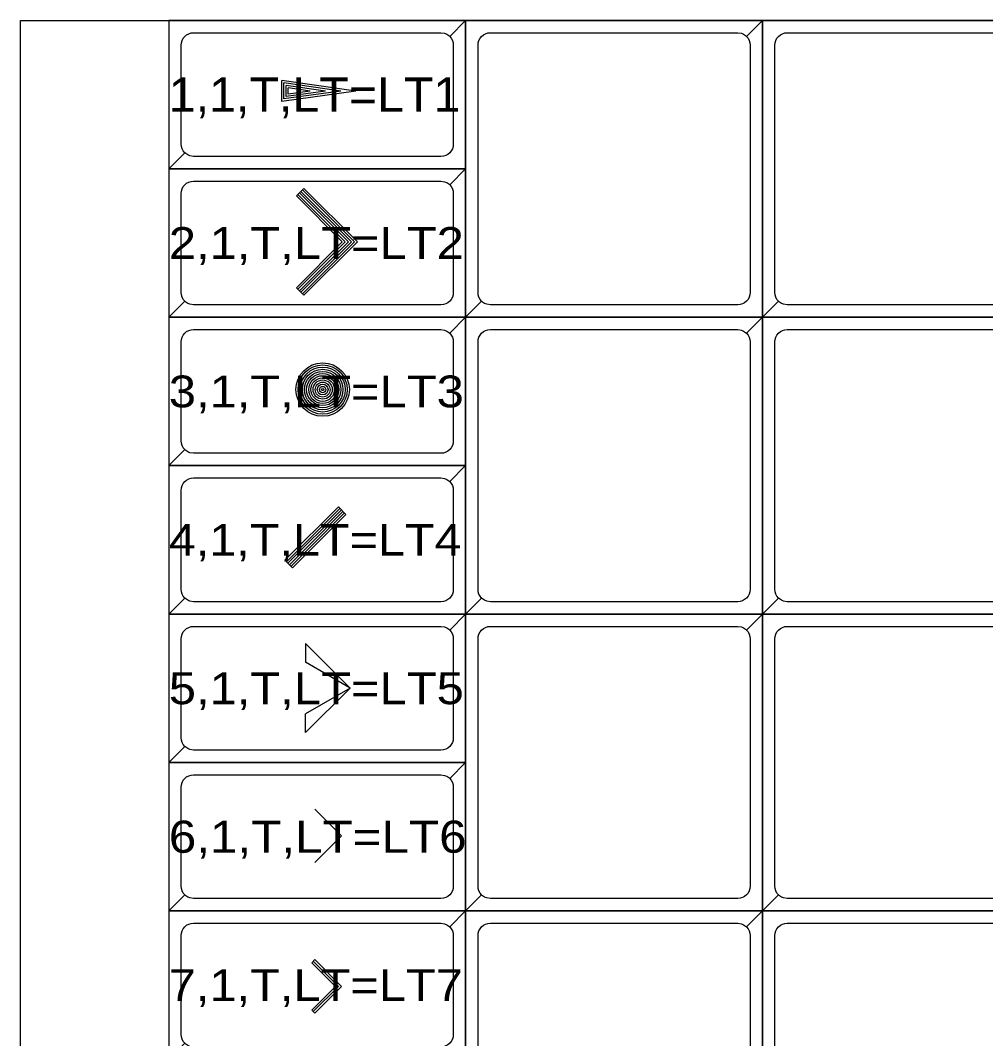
# Model space of a CAD drawing. Extents: x 67896 to 67908, y 49158.5 to 49162.6.
# Drawn here: x 67895.989 to 67897.94, y 49160.575 to 49162.633 of the extents above; entities that cross this region are included whole.
import ezdxf

# ---------------------------------------------------------------- set-up
doc = ezdxf.new("R2010")
doc.units = 0
doc.header["$LTSCALE"] = 0.02
for name, color, linetype, lineweight in [('1', 7, 'Continuous', 25), ('2', 7, 'Continuous', 25), ('3', 7, 'Continuous', 25), ('4', 7, 'Continuous', 25), ('5', 7, 'Continuous', 25)]:
    doc.layers.add(name, color=color, linetype=linetype, lineweight=lineweight)
doc.layers.add('63', color=7, linetype='Continuous')

msp = doc.modelspace()

# ---------------------------------------------------------------- linework, layer by layer
at = {"layer": '1'}
for points in [[(67896.2889, 49162.3331), (67896.8889, 49162.3331), (67896.8889, 49162.6331), (67896.2889, 49162.6331)], [(67896.8889, 49162.0331), (67897.4889, 49162.0331), (67897.4889, 49162.6331), (67896.8889, 49162.6331)], [(67897.4889, 49162.0331), (67898.0889, 49162.0331), (67898.0889, 49162.6331), (67897.4889, 49162.6331)], [(67896.2889, 49162.0331), (67896.8889, 49162.0331), (67896.8889, 49162.3331), (67896.2889, 49162.3331)], [(67896.2889, 49161.7331), (67896.8889, 49161.7331), (67896.8889, 49162.0331), (67896.2889, 49162.0331)], [(67896.8889, 49161.4331), (67897.4889, 49161.4331), (67897.4889, 49162.0331), (67896.8889, 49162.0331)], [(67897.4889, 49161.4331), (67898.0889, 49161.4331), (67898.0889, 49162.0331), (67897.4889, 49162.0331)], [(67896.2889, 49161.4331), (67896.8889, 49161.4331), (67896.8889, 49161.7331), (67896.2889, 49161.7331)], [(67896.2889, 49161.1331), (67896.8889, 49161.1331), (67896.8889, 49161.4331), (67896.2889, 49161.4331)], [(67896.8889, 49160.8331), (67897.4889, 49160.8331), (67897.4889, 49161.4331), (67896.8889, 49161.4331)], [(67897.4889, 49160.8331), (67898.0889, 49160.8331), (67898.0889, 49161.4331), (67897.4889, 49161.4331)], [(67896.2889, 49160.8331), (67896.8889, 49160.8331), (67896.8889, 49161.1331), (67896.2889, 49161.1331)], [(67896.2889, 49160.5331), (67896.8889, 49160.5331), (67896.8889, 49160.8331), (67896.2889, 49160.8331)], [(67896.8889, 49160.2331), (67897.4889, 49160.2331), (67897.4889, 49160.8331), (67896.8889, 49160.8331)], [(67897.4889, 49160.2331), (67898.0889, 49160.2331), (67898.0889, 49160.8331), (67897.4889, 49160.8331)]]:
    msp.add_lwpolyline(points, close=True, dxfattribs=at)
at = {"layer": '2'}
for points in [[(67907.9889, 49159.0331), (67895.9889, 49159.0331), (67895.9889, 49162.6331), (67907.9889, 49162.6331)], [(67896.2889, 49162.3331), (67896.8889, 49162.3331), (67896.8889, 49162.6331), (67896.2889, 49162.6331)], [(67896.8889, 49162.0331), (67897.4889, 49162.0331), (67897.4889, 49162.6331), (67896.8889, 49162.6331)], [(67897.4889, 49162.0331), (67898.0889, 49162.0331), (67898.0889, 49162.6331), (67897.4889, 49162.6331)], [(67896.2889, 49162.0331), (67896.8889, 49162.0331), (67896.8889, 49162.3331), (67896.2889, 49162.3331)], [(67896.2889, 49161.7331), (67896.8889, 49161.7331), (67896.8889, 49162.0331), (67896.2889, 49162.0331)], [(67896.8889, 49161.4331), (67897.4889, 49161.4331), (67897.4889, 49162.0331), (67896.8889, 49162.0331)], [(67897.4889, 49161.4331), (67898.0889, 49161.4331), (67898.0889, 49162.0331), (67897.4889, 49162.0331)], [(67896.2889, 49161.4331), (67896.8889, 49161.4331), (67896.8889, 49161.7331), (67896.2889, 49161.7331)], [(67896.2889, 49161.1331), (67896.8889, 49161.1331), (67896.8889, 49161.4331), (67896.2889, 49161.4331)], [(67896.8889, 49160.8331), (67897.4889, 49160.8331), (67897.4889, 49161.4331), (67896.8889, 49161.4331)], [(67897.4889, 49160.8331), (67898.0889, 49160.8331), (67898.0889, 49161.4331), (67897.4889, 49161.4331)], [(67896.2889, 49160.8331), (67896.8889, 49160.8331), (67896.8889, 49161.1331), (67896.2889, 49161.1331)], [(67896.2889, 49160.5331), (67896.8889, 49160.5331), (67896.8889, 49160.8331), (67896.2889, 49160.8331)], [(67896.8889, 49160.2331), (67897.4889, 49160.2331), (67897.4889, 49160.8331), (67896.8889, 49160.8331)], [(67897.4889, 49160.2331), (67898.0889, 49160.2331), (67898.0889, 49160.8331), (67897.4889, 49160.8331)]]:
    msp.add_lwpolyline(points, close=True, dxfattribs=at)
at = {"layer": '3'}
for points in [[(67896.8889, 49162.6331), (67896.2889, 49162.6331), (67896.2889, 49162.3331), (67896.3212, 49162.3654), (67896.3181, 49162.3692), (67896.3158, 49162.3735), (67896.3144, 49162.3782), (67896.3139, 49162.3831), (67896.3139, 49162.5831), (67896.3144, 49162.588), (67896.3158, 49162.5927), (67896.3181, 49162.597), (67896.3212, 49162.6008), (67896.3212, 49162.6008), (67896.325, 49162.6039), (67896.3293, 49162.6062), (67896.334, 49162.6076), (67896.3389, 49162.6081), (67896.8389, 49162.6081), (67896.8462, 49162.607), (67896.8507, 49162.6051), (67896.8548, 49162.6024), (67896.8566, 49162.6008)], [(67897.4889, 49162.6331), (67896.8889, 49162.6331), (67896.8889, 49162.0331), (67896.9212, 49162.0654), (67896.9181, 49162.0692), (67896.9158, 49162.0735), (67896.9144, 49162.0782), (67896.9139, 49162.0831), (67896.9139, 49162.5831), (67896.9144, 49162.588), (67896.9158, 49162.5927), (67896.9181, 49162.597), (67896.9212, 49162.6008), (67896.9212, 49162.6008), (67896.925, 49162.6039), (67896.9293, 49162.6062), (67896.934, 49162.6076), (67896.9389, 49162.6081), (67897.4389, 49162.6081), (67897.4462, 49162.607), (67897.4507, 49162.6051), (67897.4548, 49162.6024), (67897.4566, 49162.6008)], [(67898.0889, 49162.6331), (67897.4889, 49162.6331), (67897.4889, 49162.0331), (67897.5212, 49162.0654), (67897.5181, 49162.0692), (67897.5158, 49162.0735), (67897.5144, 49162.0782), (67897.5139, 49162.0831), (67897.5139, 49162.5831), (67897.5144, 49162.588), (67897.5158, 49162.5927), (67897.5181, 49162.597), (67897.5212, 49162.6008), (67897.5212, 49162.6008), (67897.525, 49162.6039), (67897.5293, 49162.6062), (67897.534, 49162.6076), (67897.5389, 49162.6081), (67898.0389, 49162.6081), (67898.0462, 49162.607), (67898.0507, 49162.6051), (67898.0548, 49162.6024), (67898.0566, 49162.6008)], [(67896.8889, 49162.3331), (67896.2889, 49162.3331), (67896.2889, 49162.0331), (67896.3212, 49162.0654), (67896.3181, 49162.0692), (67896.3158, 49162.0735), (67896.3144, 49162.0782), (67896.3139, 49162.0831), (67896.3139, 49162.2831), (67896.3144, 49162.288), (67896.3158, 49162.2927), (67896.3181, 49162.297), (67896.3212, 49162.3008), (67896.3212, 49162.3008), (67896.325, 49162.3039), (67896.3293, 49162.3062), (67896.334, 49162.3076), (67896.3389, 49162.3081), (67896.8389, 49162.3081), (67896.8462, 49162.307), (67896.8507, 49162.3051), (67896.8548, 49162.3024), (67896.8566, 49162.3008)], [(67896.8889, 49162.0331), (67896.2889, 49162.0331), (67896.2889, 49161.7331), (67896.3212, 49161.7654), (67896.3181, 49161.7692), (67896.3158, 49161.7735), (67896.3144, 49161.7782), (67896.3139, 49161.7831), (67896.3139, 49161.9831), (67896.3144, 49161.988), (67896.3158, 49161.9927), (67896.3181, 49161.997), (67896.3212, 49162.0008), (67896.3212, 49162.0008), (67896.325, 49162.0039), (67896.3293, 49162.0062), (67896.334, 49162.0076), (67896.3389, 49162.0081), (67896.8389, 49162.0081), (67896.8462, 49162.007), (67896.8507, 49162.0051), (67896.8548, 49162.0024), (67896.8566, 49162.0008)], [(67897.4889, 49162.0331), (67896.8889, 49162.0331), (67896.8889, 49161.4331), (67896.9212, 49161.4654), (67896.9181, 49161.4692), (67896.9158, 49161.4735), (67896.9144, 49161.4782), (67896.9139, 49161.4831), (67896.9139, 49161.9831), (67896.9144, 49161.988), (67896.9158, 49161.9927), (67896.9181, 49161.997), (67896.9212, 49162.0008), (67896.9212, 49162.0008), (67896.925, 49162.0039), (67896.9293, 49162.0062), (67896.934, 49162.0076), (67896.9389, 49162.0081), (67897.4389, 49162.0081), (67897.4462, 49162.007), (67897.4507, 49162.0051), (67897.4548, 49162.0024), (67897.4566, 49162.0008)], [(67898.0889, 49162.0331), (67897.4889, 49162.0331), (67897.4889, 49161.4331), (67897.5212, 49161.4654), (67897.5181, 49161.4692), (67897.5158, 49161.4735), (67897.5144, 49161.4782), (67897.5139, 49161.4831), (67897.5139, 49161.9831), (67897.5144, 49161.988), (67897.5158, 49161.9927), (67897.5181, 49161.997), (67897.5212, 49162.0008), (67897.5212, 49162.0008), (67897.525, 49162.0039), (67897.5293, 49162.0062), (67897.534, 49162.0076), (67897.5389, 49162.0081), (67898.0389, 49162.0081), (67898.0462, 49162.007), (67898.0507, 49162.0051), (67898.0548, 49162.0024), (67898.0566, 49162.0008)], [(67896.8889, 49161.7331), (67896.2889, 49161.7331), (67896.2889, 49161.4331), (67896.3212, 49161.4654), (67896.3181, 49161.4692), (67896.3158, 49161.4735), (67896.3144, 49161.4782), (67896.3139, 49161.4831), (67896.3139, 49161.6831), (67896.3144, 49161.688), (67896.3158, 49161.6927), (67896.3181, 49161.697), (67896.3212, 49161.7008), (67896.3212, 49161.7008), (67896.325, 49161.7039), (67896.3293, 49161.7062), (67896.334, 49161.7076), (67896.3389, 49161.7081), (67896.8389, 49161.7081), (67896.8462, 49161.707), (67896.8507, 49161.7051), (67896.8548, 49161.7024), (67896.8566, 49161.7008)], [(67896.8889, 49161.4331), (67896.2889, 49161.4331), (67896.2889, 49161.1331), (67896.3212, 49161.1654), (67896.3181, 49161.1692), (67896.3158, 49161.1735), (67896.3144, 49161.1782), (67896.3139, 49161.1831), (67896.3139, 49161.3831), (67896.3144, 49161.388), (67896.3158, 49161.3927), (67896.3181, 49161.397), (67896.3212, 49161.4008), (67896.3212, 49161.4008), (67896.325, 49161.4039), (67896.3293, 49161.4062), (67896.334, 49161.4076), (67896.3389, 49161.4081), (67896.8389, 49161.4081), (67896.8462, 49161.407), (67896.8507, 49161.4051), (67896.8548, 49161.4024), (67896.8566, 49161.4008)], [(67897.4889, 49161.4331), (67896.8889, 49161.4331), (67896.8889, 49160.8331), (67896.9212, 49160.8654), (67896.9181, 49160.8692), (67896.9158, 49160.8735), (67896.9144, 49160.8782), (67896.9139, 49160.8831), (67896.9139, 49161.3831), (67896.9144, 49161.388), (67896.9158, 49161.3927), (67896.9181, 49161.397), (67896.9212, 49161.4008), (67896.9212, 49161.4008), (67896.925, 49161.4039), (67896.9293, 49161.4062), (67896.934, 49161.4076), (67896.9389, 49161.4081), (67897.4389, 49161.4081), (67897.4462, 49161.407), (67897.4507, 49161.4051), (67897.4548, 49161.4024), (67897.4566, 49161.4008)], [(67898.0889, 49161.4331), (67897.4889, 49161.4331), (67897.4889, 49160.8331), (67897.5212, 49160.8654), (67897.5181, 49160.8692), (67897.5158, 49160.8735), (67897.5144, 49160.8782), (67897.5139, 49160.8831), (67897.5139, 49161.3831), (67897.5144, 49161.388), (67897.5158, 49161.3927), (67897.5181, 49161.397), (67897.5212, 49161.4008), (67897.5212, 49161.4008), (67897.525, 49161.4039), (67897.5293, 49161.4062), (67897.534, 49161.4076), (67897.5389, 49161.4081), (67898.0389, 49161.4081), (67898.0462, 49161.407), (67898.0507, 49161.4051), (67898.0548, 49161.4024), (67898.0566, 49161.4008)], [(67896.8889, 49161.1331), (67896.2889, 49161.1331), (67896.2889, 49160.8331), (67896.3212, 49160.8654), (67896.3181, 49160.8692), (67896.3158, 49160.8735), (67896.3144, 49160.8782), (67896.3139, 49160.8831), (67896.3139, 49161.0831), (67896.3144, 49161.088), (67896.3158, 49161.0927), (67896.3181, 49161.097), (67896.3212, 49161.1008), (67896.3212, 49161.1008), (67896.325, 49161.1039), (67896.3293, 49161.1062), (67896.334, 49161.1076), (67896.3389, 49161.1081), (67896.8389, 49161.1081), (67896.8462, 49161.107), (67896.8507, 49161.1051), (67896.8548, 49161.1024), (67896.8566, 49161.1008)], [(67896.8889, 49160.8331), (67896.2889, 49160.8331), (67896.2889, 49160.5331), (67896.3212, 49160.5654), (67896.3181, 49160.5692), (67896.3158, 49160.5735), (67896.3144, 49160.5782), (67896.3139, 49160.5831), (67896.3139, 49160.7831), (67896.3144, 49160.788), (67896.3158, 49160.7927), (67896.3181, 49160.797), (67896.3212, 49160.8008), (67896.3212, 49160.8008), (67896.325, 49160.8039), (67896.3293, 49160.8062), (67896.334, 49160.8076), (67896.3389, 49160.8081), (67896.8389, 49160.8081), (67896.8462, 49160.807), (67896.8507, 49160.8051), (67896.8548, 49160.8024), (67896.8566, 49160.8008)], [(67897.4889, 49160.8331), (67896.8889, 49160.8331), (67896.8889, 49160.2331), (67896.9212, 49160.2654), (67896.9181, 49160.2692), (67896.9158, 49160.2735), (67896.9144, 49160.2782), (67896.9139, 49160.2831), (67896.9139, 49160.7831), (67896.9144, 49160.788), (67896.9158, 49160.7927), (67896.9181, 49160.797), (67896.9212, 49160.8008), (67896.9212, 49160.8008), (67896.925, 49160.8039), (67896.9293, 49160.8062), (67896.934, 49160.8076), (67896.9389, 49160.8081), (67897.4389, 49160.8081), (67897.4462, 49160.807), (67897.4507, 49160.8051), (67897.4548, 49160.8024), (67897.4566, 49160.8008)], [(67898.0889, 49160.8331), (67897.4889, 49160.8331), (67897.4889, 49160.2331), (67897.5212, 49160.2654), (67897.5181, 49160.2692), (67897.5158, 49160.2735), (67897.5144, 49160.2782), (67897.5139, 49160.2831), (67897.5139, 49160.7831), (67897.5144, 49160.788), (67897.5158, 49160.7927), (67897.5181, 49160.797), (67897.5212, 49160.8008), (67897.5212, 49160.8008), (67897.525, 49160.8039), (67897.5293, 49160.8062), (67897.534, 49160.8076), (67897.5389, 49160.8081), (67898.0389, 49160.8081), (67898.0462, 49160.807), (67898.0507, 49160.8051), (67898.0548, 49160.8024), (67898.0566, 49160.8008)]]:
    msp.add_lwpolyline(points, close=True, dxfattribs=at)
at = {"layer": '4'}
for points in [[(67896.2889, 49162.3331), (67896.8889, 49162.3331), (67896.8889, 49162.6331), (67896.8566, 49162.6008), (67896.8597, 49162.597), (67896.862, 49162.5927), (67896.8634, 49162.588), (67896.8639, 49162.5831), (67896.8639, 49162.3831), (67896.8634, 49162.3782), (67896.862, 49162.3735), (67896.8597, 49162.3692), (67896.8566, 49162.3654), (67896.8566, 49162.3654), (67896.8528, 49162.3623), (67896.8485, 49162.36), (67896.8438, 49162.3586), (67896.8389, 49162.3581), (67896.3389, 49162.3581), (67896.3316, 49162.3592), (67896.3271, 49162.3611), (67896.323, 49162.3638), (67896.3212, 49162.3654)], [(67896.8889, 49162.0331), (67897.4889, 49162.0331), (67897.4889, 49162.6331), (67897.4566, 49162.6008), (67897.4597, 49162.597), (67897.462, 49162.5927), (67897.4634, 49162.588), (67897.4639, 49162.5831), (67897.4639, 49162.0831), (67897.4634, 49162.0782), (67897.462, 49162.0735), (67897.4597, 49162.0692), (67897.4566, 49162.0654), (67897.4566, 49162.0654), (67897.4528, 49162.0623), (67897.4485, 49162.06), (67897.4438, 49162.0586), (67897.4389, 49162.0581), (67896.9389, 49162.0581), (67896.9316, 49162.0592), (67896.9271, 49162.0611), (67896.923, 49162.0638), (67896.9212, 49162.0654)], [(67897.4889, 49162.0331), (67898.0889, 49162.0331), (67898.0889, 49162.6331), (67898.0566, 49162.6008), (67898.0597, 49162.597), (67898.062, 49162.5927), (67898.0634, 49162.588), (67898.0639, 49162.5831), (67898.0639, 49162.0831), (67898.0634, 49162.0782), (67898.062, 49162.0735), (67898.0597, 49162.0692), (67898.0566, 49162.0654), (67898.0566, 49162.0654), (67898.0528, 49162.0623), (67898.0485, 49162.06), (67898.0438, 49162.0586), (67898.0389, 49162.0581), (67897.5389, 49162.0581), (67897.5316, 49162.0592), (67897.5271, 49162.0611), (67897.523, 49162.0638), (67897.5212, 49162.0654)], [(67896.2889, 49162.0331), (67896.8889, 49162.0331), (67896.8889, 49162.3331), (67896.8566, 49162.3008), (67896.8597, 49162.297), (67896.862, 49162.2927), (67896.8634, 49162.288), (67896.8639, 49162.2831), (67896.8639, 49162.0831), (67896.8634, 49162.0782), (67896.862, 49162.0735), (67896.8597, 49162.0692), (67896.8566, 49162.0654), (67896.8566, 49162.0654), (67896.8528, 49162.0623), (67896.8485, 49162.06), (67896.8438, 49162.0586), (67896.8389, 49162.0581), (67896.3389, 49162.0581), (67896.3316, 49162.0592), (67896.3271, 49162.0611), (67896.323, 49162.0638), (67896.3212, 49162.0654)], [(67896.2889, 49161.7331), (67896.8889, 49161.7331), (67896.8889, 49162.0331), (67896.8566, 49162.0008), (67896.8597, 49161.997), (67896.862, 49161.9927), (67896.8634, 49161.988), (67896.8639, 49161.9831), (67896.8639, 49161.7831), (67896.8634, 49161.7782), (67896.862, 49161.7735), (67896.8597, 49161.7692), (67896.8566, 49161.7654), (67896.8566, 49161.7654), (67896.8528, 49161.7623), (67896.8485, 49161.76), (67896.8438, 49161.7586), (67896.8389, 49161.7581), (67896.3389, 49161.7581), (67896.3316, 49161.7592), (67896.3271, 49161.7611), (67896.323, 49161.7638), (67896.3212, 49161.7654)], [(67896.8889, 49161.4331), (67897.4889, 49161.4331), (67897.4889, 49162.0331), (67897.4566, 49162.0008), (67897.4597, 49161.997), (67897.462, 49161.9927), (67897.4634, 49161.988), (67897.4639, 49161.9831), (67897.4639, 49161.4831), (67897.4634, 49161.4782), (67897.462, 49161.4735), (67897.4597, 49161.4692), (67897.4566, 49161.4654), (67897.4566, 49161.4654), (67897.4528, 49161.4623), (67897.4485, 49161.46), (67897.4438, 49161.4586), (67897.4389, 49161.4581), (67896.9389, 49161.4581), (67896.9316, 49161.4592), (67896.9271, 49161.4611), (67896.923, 49161.4638), (67896.9212, 49161.4654)], [(67897.4889, 49161.4331), (67898.0889, 49161.4331), (67898.0889, 49162.0331), (67898.0566, 49162.0008), (67898.0597, 49161.997), (67898.062, 49161.9927), (67898.0634, 49161.988), (67898.0639, 49161.9831), (67898.0639, 49161.4831), (67898.0634, 49161.4782), (67898.062, 49161.4735), (67898.0597, 49161.4692), (67898.0566, 49161.4654), (67898.0566, 49161.4654), (67898.0528, 49161.4623), (67898.0485, 49161.46), (67898.0438, 49161.4586), (67898.0389, 49161.4581), (67897.5389, 49161.4581), (67897.5316, 49161.4592), (67897.5271, 49161.4611), (67897.523, 49161.4638), (67897.5212, 49161.4654)], [(67896.2889, 49161.4331), (67896.8889, 49161.4331), (67896.8889, 49161.7331), (67896.8566, 49161.7008), (67896.8597, 49161.697), (67896.862, 49161.6927), (67896.8634, 49161.688), (67896.8639, 49161.6831), (67896.8639, 49161.4831), (67896.8634, 49161.4782), (67896.862, 49161.4735), (67896.8597, 49161.4692), (67896.8566, 49161.4654), (67896.8566, 49161.4654), (67896.8528, 49161.4623), (67896.8485, 49161.46), (67896.8438, 49161.4586), (67896.8389, 49161.4581), (67896.3389, 49161.4581), (67896.3316, 49161.4592), (67896.3271, 49161.4611), (67896.323, 49161.4638), (67896.3212, 49161.4654)], [(67896.2889, 49161.1331), (67896.8889, 49161.1331), (67896.8889, 49161.4331), (67896.8566, 49161.4008), (67896.8597, 49161.397), (67896.862, 49161.3927), (67896.8634, 49161.388), (67896.8639, 49161.3831), (67896.8639, 49161.1831), (67896.8634, 49161.1782), (67896.862, 49161.1735), (67896.8597, 49161.1692), (67896.8566, 49161.1654), (67896.8566, 49161.1654), (67896.8528, 49161.1623), (67896.8485, 49161.16), (67896.8438, 49161.1586), (67896.8389, 49161.1581), (67896.3389, 49161.1581), (67896.3316, 49161.1592), (67896.3271, 49161.1611), (67896.323, 49161.1638), (67896.3212, 49161.1654)], [(67896.8889, 49160.8331), (67897.4889, 49160.8331), (67897.4889, 49161.4331), (67897.4566, 49161.4008), (67897.4597, 49161.397), (67897.462, 49161.3927), (67897.4634, 49161.388), (67897.4639, 49161.3831), (67897.4639, 49160.8831), (67897.4634, 49160.8782), (67897.462, 49160.8735), (67897.4597, 49160.8692), (67897.4566, 49160.8654), (67897.4566, 49160.8654), (67897.4528, 49160.8623), (67897.4485, 49160.86), (67897.4438, 49160.8586), (67897.4389, 49160.8581), (67896.9389, 49160.8581), (67896.9316, 49160.8592), (67896.9271, 49160.8611), (67896.923, 49160.8638), (67896.9212, 49160.8654)], [(67897.4889, 49160.8331), (67898.0889, 49160.8331), (67898.0889, 49161.4331), (67898.0566, 49161.4008), (67898.0597, 49161.397), (67898.062, 49161.3927), (67898.0634, 49161.388), (67898.0639, 49161.3831), (67898.0639, 49160.8831), (67898.0634, 49160.8782), (67898.062, 49160.8735), (67898.0597, 49160.8692), (67898.0566, 49160.8654), (67898.0566, 49160.8654), (67898.0528, 49160.8623), (67898.0485, 49160.86), (67898.0438, 49160.8586), (67898.0389, 49160.8581), (67897.5389, 49160.8581), (67897.5316, 49160.8592), (67897.5271, 49160.8611), (67897.523, 49160.8638), (67897.5212, 49160.8654)], [(67896.2889, 49160.8331), (67896.8889, 49160.8331), (67896.8889, 49161.1331), (67896.8566, 49161.1008), (67896.8597, 49161.097), (67896.862, 49161.0927), (67896.8634, 49161.088), (67896.8639, 49161.0831), (67896.8639, 49160.8831), (67896.8634, 49160.8782), (67896.862, 49160.8735), (67896.8597, 49160.8692), (67896.8566, 49160.8654), (67896.8566, 49160.8654), (67896.8528, 49160.8623), (67896.8485, 49160.86), (67896.8438, 49160.8586), (67896.8389, 49160.8581), (67896.3389, 49160.8581), (67896.3316, 49160.8592), (67896.3271, 49160.8611), (67896.323, 49160.8638), (67896.3212, 49160.8654)], [(67896.2889, 49160.5331), (67896.8889, 49160.5331), (67896.8889, 49160.8331), (67896.8566, 49160.8008), (67896.8597, 49160.797), (67896.862, 49160.7927), (67896.8634, 49160.788), (67896.8639, 49160.7831), (67896.8639, 49160.5831), (67896.8634, 49160.5782), (67896.862, 49160.5735), (67896.8597, 49160.5692), (67896.8566, 49160.5654), (67896.8566, 49160.5654), (67896.8528, 49160.5623), (67896.8485, 49160.56), (67896.8438, 49160.5586), (67896.8389, 49160.5581), (67896.3389, 49160.5581), (67896.3316, 49160.5592), (67896.3271, 49160.5611), (67896.323, 49160.5638), (67896.3212, 49160.5654)], [(67896.8889, 49160.2331), (67897.4889, 49160.2331), (67897.4889, 49160.8331), (67897.4566, 49160.8008), (67897.4597, 49160.797), (67897.462, 49160.7927), (67897.4634, 49160.788), (67897.4639, 49160.7831), (67897.4639, 49160.2831), (67897.4634, 49160.2782), (67897.462, 49160.2735), (67897.4597, 49160.2692), (67897.4566, 49160.2654), (67897.4566, 49160.2654), (67897.4528, 49160.2623), (67897.4485, 49160.26), (67897.4438, 49160.2586), (67897.4389, 49160.2581), (67896.9389, 49160.2581), (67896.9316, 49160.2592), (67896.9271, 49160.2611), (67896.923, 49160.2638), (67896.9212, 49160.2654)]]:
    msp.add_lwpolyline(points, close=True, dxfattribs=at)
at = {"layer": '5'}
for p, q in [((67896.5172, 49162.4692), (67896.5172, 49162.5115)), ((67896.6672, 49162.4899), (67896.5172, 49162.5115)), ((67896.6363, 49162.49), (67896.5215, 49162.5065)), ((67896.5215, 49162.4742), (67896.5215, 49162.5065)), ((67896.6054, 49162.4901), (67896.5258, 49162.5016)), ((67896.5258, 49162.4791), (67896.5258, 49162.5016)), ((67896.5744, 49162.4902), (67896.5302, 49162.4966)), ((67896.5302, 49162.4841), (67896.5302, 49162.4966)), ((67896.6672, 49162.4899), (67896.5172, 49162.4692)), ((67896.6363, 49162.49), (67896.5215, 49162.4742)), ((67896.6054, 49162.4901), (67896.5258, 49162.4791)), ((67896.5744, 49162.4902), (67896.5302, 49162.4841)), ((67896.5621, 49162.2934), (67896.5468, 49162.2781)), ((67896.664, 49162.1854), (67896.559, 49162.2903)), ((67896.6701, 49162.1854), (67896.5621, 49162.2934)), ((67896.6396, 49162.1854), (67896.5468, 49162.2781)), ((67896.6457, 49162.1854), (67896.5499, 49162.2812)), ((67896.6518, 49162.1854), (67896.5529, 49162.2842)), ((67896.6579, 49162.1854), (67896.556, 49162.2873)), ((67896.6396, 49162.1854), (67896.5468, 49162.0927)), ((67896.6457, 49162.1854), (67896.5499, 49162.0896)), ((67896.6518, 49162.1854), (67896.5529, 49162.0866)), ((67896.6579, 49162.1854), (67896.556, 49162.0835)), ((67896.664, 49162.1854), (67896.559, 49162.0805)), ((67896.6701, 49162.1854), (67896.5621, 49162.0774)), ((67896.5621, 49162.0774), (67896.5468, 49162.0927)), ((67896.6316, 49161.6498), (67896.5235, 49161.5417)), ((67896.6346, 49161.6467), (67896.5266, 49161.5387)), ((67896.6377, 49161.6436), (67896.5297, 49161.5356)), ((67896.6407, 49161.6406), (67896.5327, 49161.5326)), ((67896.6438, 49161.6375), (67896.5358, 49161.5295)), ((67896.6468, 49161.6345), (67896.5388, 49161.5265)), ((67896.6468, 49161.6345), (67896.6316, 49161.6498)), ((67896.5388, 49161.5265), (67896.5236, 49161.5418)), ((67896.6555, 49161.2836), (67896.5655, 49161.3736)), ((67896.5655, 49161.3736), (67896.5655, 49161.3356)), ((67896.6555, 49161.2836), (67896.5655, 49161.3356)), ((67896.6555, 49161.2836), (67896.5655, 49161.1936)), ((67896.6555, 49161.2836), (67896.5655, 49161.2316)), ((67896.5655, 49161.1936), (67896.5655, 49161.2316)), ((67896.6379, 49160.985), (67896.5839, 49161.039)), ((67896.6379, 49160.985), (67896.5839, 49160.931)), ((67896.5839, 49160.7345), (67896.5778, 49160.7284)), ((67896.6257, 49160.6805), (67896.5778, 49160.7284)), ((67896.6318, 49160.6805), (67896.5808, 49160.7314)), ((67896.6379, 49160.6805), (67896.5839, 49160.7345)), ((67896.6257, 49160.6805), (67896.5778, 49160.6326)), ((67896.6318, 49160.6805), (67896.5808, 49160.6296)), ((67896.6379, 49160.6805), (67896.5839, 49160.6265)), ((67896.5839, 49160.6265), (67896.5778, 49160.6326))]:
    msp.add_line(p, q, dxfattribs=at)
for radius in [0.054, 0.0497, 0.0454, 0.041, 0.0367, 0.0324, 0.0281, 0.0238, 0.0194, 0.0151, 0.0108, 0.00648, 0.00216]:
    msp.add_circle((67896.5999, 49161.8868), radius, dxfattribs=at)

# ---------------------------------------------------------------- texts
at = {"layer": '63'}
for s, height, width, p in [('1,1,T,LT=LT1', 0.0696, 1.05, (67896.2889, 49162.4483)), ('2,1,T,LT=LT2', 0.0643, 1.15, (67896.2889, 49162.1509)), ('3,1,T,LT=LT3', 0.0643, 1.15, (67896.2889, 49161.8509)), ('4,1,T,LT=LT4', 0.0638, 1.15, (67896.2889, 49161.5512)), ('5,1,T,LT=LT5', 0.0643, 1.15, (67896.2889, 49161.2509)), ('6,1,T,LT=LT6', 0.0649, 1.15, (67896.2889, 49160.9506)), ('7,1,T,LT=LT7', 0.0641, 1.15, (67896.2889, 49160.651))]:
    msp.add_text(s, height=height, dxfattribs=dict(at, width=width)).set_placement(p)

doc.saveas('drawing.dxf')
